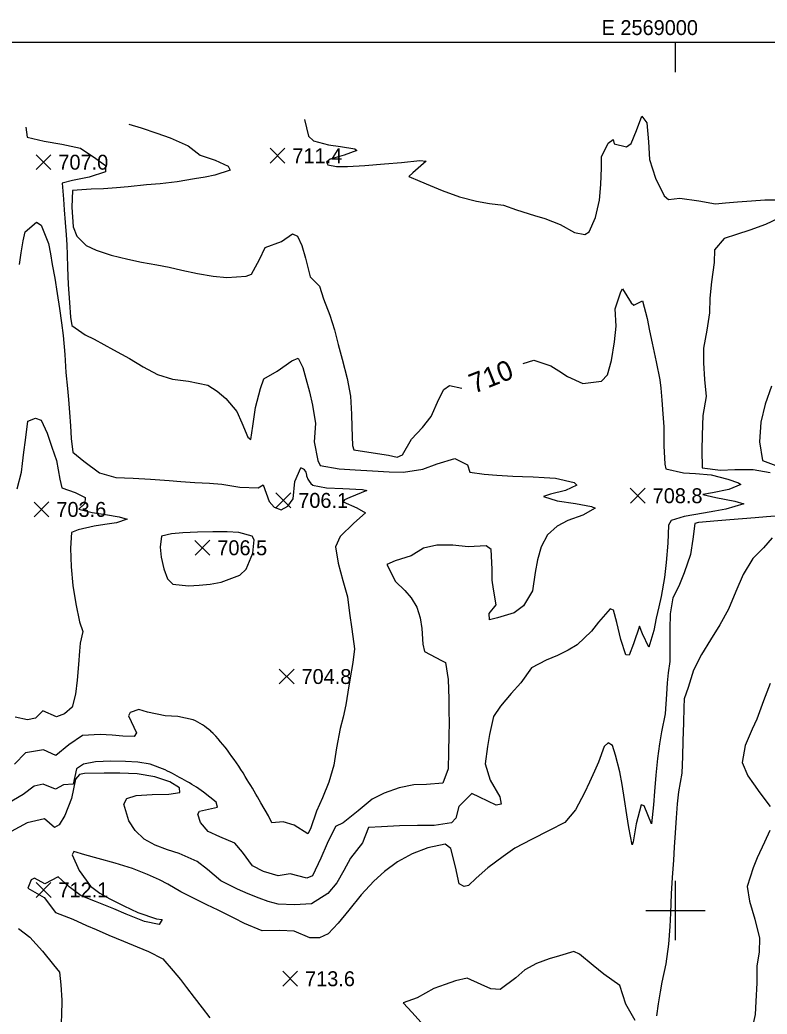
# Model space of a CAD drawing. Extents: x 2566079 to 2571326, y 424054 to 426896.
# Drawn here: x 2568340 to 2569092, y 425896 to 426896 of the extents above; entities that cross this region are included whole.
import ezdxf

# ---------------------------------------------------------------- set-up
doc = ezdxf.new("R2010")
doc.units = 0
for name, color, linetype in [('Contour_ADS_Label_Major', 7, 'Continuous'), ('Contour_ADS_Major', 7, 'Continuous'), ('Contour_ADS_Minor', 7, 'Continuous'), ('Contour_ADS_Spot_Elevation', 7, 'Continuous'), ('Contour_ADS_State_Plane_Border', 7, 'Continuous'), ('Contour_ADS_Tick', 7, 'Continuous')]:
    doc.layers.add(name, color=color, linetype=linetype)

# ---------------------------------------------------------------- blocks, each defined once
blk = doc.blocks.new('S890')
at = {"layer": 'Contour_ADS_Tick'}
for p, q in [((0, -0.5), (0, 0.5)), ((-0.5, 0), (0.5, 0))]:
    blk.add_line(p, q, dxfattribs=at)
blk = doc.blocks.new('S750')
at = {"layer": 'Contour_ADS_Spot_Elevation'}
for p, q in [((-0.5, 0.498), (0.5, -0.498)), ((-0.498, -0.5), (0.498, 0.5))]:
    blk.add_line(p, q, dxfattribs=at)

msp = doc.modelspace()

# ---------------------------------------------------------------- linework, layer by layer
at = {"layer": 'Contour_ADS_Major'}
for points in [[(2568449.5, 426791.4), (2568461.9, 426787.7), (2568477.7, 426782.6), (2568490.9, 426777.6), (2568509, 426769.6), (2568521.3, 426760.3), (2568536.4, 426755.2), (2568549.4, 426749.1), (2568551.5, 426745.1), (2568536.1, 426740.1), (2568526.1, 426738.3), (2568515.4, 426736.5), (2568497.9, 426733.6), (2568480.8, 426731.3), (2568467.3, 426730.4), (2568448.8, 426728.4), (2568437.1, 426727.3), (2568424, 426726.5), (2568411.4, 426725.9), (2568392.7, 426724.6), (2568392, 426708), (2568393.4, 426688.1), (2568397, 426678.9), (2568406.4, 426669.4), (2568416.6, 426664.6), (2568431.7, 426659.8), (2568448.3, 426655.7), (2568462.1, 426652.6), (2568477.5, 426649.8), (2568490.1, 426647.4), (2568502.9, 426644.6), (2568518.5, 426641.2), (2568534.2, 426638.5), (2568548, 426637.2), (2568567.6, 426638.4), (2568573, 426640.6), (2568580.9, 426655.4), (2568586.8, 426667.5), (2568603.3, 426673.3), (2568614.3, 426681.2), (2568619.3, 426678.6), (2568623.7, 426669.3), (2568627.3, 426656.6), (2568631.9, 426637.7), (2568641.5, 426628.4), (2568645.5, 426615.6), (2568651.8, 426599.3), (2568656.6, 426584.5), (2568660.3, 426569.6), (2568664.4, 426554.8), (2568669.3, 426535.4), (2568672.8, 426517.6), (2568673.5, 426499.5), (2568673.9, 426486.4), (2568674.6, 426468.2), (2568675.9, 426463.8), (2568691.2, 426461.3), (2568710.9, 426458.3), (2568719.6, 426456.3), (2568725.1, 426458.6), (2568734.1, 426474.4), (2568745.1, 426486.3), (2568754, 426497.3), (2568761.7, 426514.8), (2568766.7, 426524.5), (2568772.5, 426528.6), (2568784.7, 426525.9)], [(2568846.6, 426550.5), (2568857.2, 426554.1), (2568874.5, 426548.3), (2568882.4, 426543.3), (2568891.3, 426537.4), (2568906.7, 426530.6), (2568925.4, 426532.7), (2568931.6, 426539.2), (2568935.7, 426553.5), (2568938.6, 426572.5), (2568940.4, 426588.1), (2568939.4, 426605.5), (2568945.1, 426622.6), (2568946.6, 426625.7), (2568955.3, 426611.7), (2568958, 426609.2), (2568966.6, 426613.6), (2568971.5, 426596), (2568973.9, 426583.5), (2568976.4, 426571), (2568980.6, 426552.1), (2568984.1, 426534.3), (2568985.1, 426525.9), (2568986.2, 426513.7), (2568987.3, 426499.8), (2568988.1, 426487), (2568988.4, 426467.6), (2568989.1, 426449.2), (2568990.4, 426444.6), (2569008, 426440.5), (2569020.2, 426439.8), (2569036.1, 426438.4), (2569052.8, 426434.2), (2569063.3, 426430.6), (2569065.8, 426428.7), (2569053.6, 426423.7), (2569037.2, 426420.5), (2569027.5, 426418.7), (2569040.6, 426415.8), (2569059.8, 426412), (2569068.7, 426409.2), (2569050.8, 426403.8), (2569039.7, 426401.8), (2569028.1, 426399.8), (2569008.7, 426396.6), (2568995.8, 426392.5), (2568992.8, 426387.8), (2568992.3, 426369.6), (2568990.5, 426350.2), (2568989, 426335.2), (2568985.7, 426316), (2568983.3, 426305.7), (2568980.7, 426294.3), (2568978.1, 426281.9), (2568973.3, 426265.2), (2568966.7, 426278.6), (2568963.8, 426286.2), (2568957.8, 426268.3), (2568953.5, 426256.9), (2568950.1, 426257.3), (2568945, 426272.7), (2568941, 426289.8), (2568937.6, 426302.3), (2568934.2, 426303.5), (2568922.5, 426290.3), (2568915.5, 426281), (2568900.9, 426267.4), (2568891.9, 426262.1), (2568881, 426256.8), (2568869.9, 426251.9), (2568855.1, 426244.1), (2568844.2, 426229), (2568834.6, 426218.4), (2568823.6, 426205.6), (2568816.8, 426195.2), (2568812.5, 426177.2), (2568810.7, 426165.2), (2568808.3, 426147.7), (2568813.4, 426131.3), (2568822.9, 426114.3), (2568824.4, 426106.9), (2568819.5, 426106.1), (2568802.7, 426114.1), (2568795, 426117.7), (2568781.9, 426104.7), (2568778.9, 426092.9), (2568774.3, 426088.1), (2568756.9, 426085.7), (2568740.3, 426085.6), (2568722, 426085.3), (2568703.9, 426084.3), (2568690.9, 426083.4), (2568684.6, 426068), (2568672.7, 426052.6), (2568665.9, 426040.2), (2568658.9, 426027.8), (2568649.7, 426017.1), (2568633.3, 426006.6), (2568616.1, 426005.8), (2568599.7, 426006.3), (2568589.7, 426009.1)], [(2568589.7, 426009.1), (2568580.5, 426012.5), (2568569.7, 426016.8), (2568558.8, 426021.4), (2568541.9, 426029.7), (2568528.7, 426041.3), (2568518.3, 426049.2), (2568500, 426057.2), (2568488.2, 426061), (2568476, 426065.6), (2568464.8, 426071.9), (2568455.8, 426080.4), (2568449.3, 426090.1), (2568444.2, 426107.1), (2568447.5, 426112.7), (2568456.9, 426115.8), (2568472.8, 426116.8), (2568489.6, 426117.1), (2568500.6, 426118.9), (2568500.3, 426123.5), (2568490.8, 426129.5), (2568475.5, 426134.6), (2568457.8, 426137.4), (2568440.2, 426138.2), (2568424.6, 426138.2), (2568404.7, 426138), (2568399.6, 426137), (2568395.8, 426132.1), (2568391.5, 426112.8), (2568384.9, 426095.5), (2568379.1, 426086.2), (2568374.5, 426083.6), (2568364.3, 426092.1), (2568347, 426088.2), (2568330.8, 426079.5)], [(2568338.3, 425981.8), (2568349.5, 425973), (2568362.5, 425958.9), (2568373.6, 425945.3), (2568379.5, 425938), (2568380.8, 425925.3), (2568381.9, 425909.7), (2568381.7, 425893.8), (2568380.6, 425877.8), (2568377.6, 425861.3), (2568372.3, 425845.4), (2568371.3, 425838.1), (2568378.8, 425820.9), (2568385.3, 425812.2), (2568397.8, 425805.3), (2568405.8, 425802.5), (2568406.5, 425802.3)]]:
    msp.add_lwpolyline(points, dxfattribs=at)
at = {"layer": 'Contour_ADS_Minor'}
for points in [[(2568626.3, 426796.2), (2568630.5, 426779.4), (2568635.5, 426774.6), (2568650.4, 426770.6), (2568662.7, 426768.9), (2568677.1, 426766.6), (2568679, 426765), (2568666.1, 426760.3), (2568652.3, 426756.1), (2568648.5, 426753.4), (2568649.7, 426750.5), (2568658.4, 426749), (2568669.7, 426749), (2568687.1, 426750), (2568706.8, 426751.5), (2568723.9, 426753), (2568742.5, 426755), (2568748.7, 426754.1), (2568735.3, 426742.4), (2568731.4, 426738.9), (2568742.5, 426734.1), (2568752.9, 426729.6), (2568765.1, 426724.6), (2568782.5, 426718.2), (2568799.5, 426714), (2568812.7, 426711.8), (2568826.7, 426709.8), (2568840, 426705.2), (2568858, 426699.4), (2568868.3, 426696.6), (2568883.7, 426690.6), (2568898.3, 426682.6), (2568908.6, 426680.5), (2568913.2, 426683.1), (2568919.3, 426697.5), (2568923.6, 426715.1), (2568924.7, 426730.9), (2568925.6, 426747.4), (2568925.4, 426758.5), (2568932.1, 426772.5), (2568937.2, 426775.9), (2568938.3, 426771.8), (2568950.8, 426768.7), (2568955.3, 426772.1), (2568960.7, 426785.1), (2568966.1, 426799.4), (2568971, 426792.9), (2568972.7, 426773.8), (2568973.9, 426755.9), (2568979.9, 426737.3), (2568988.5, 426719.4), (2568993.1, 426715.5), (2569004.4, 426716.9), (2569023.5, 426714.4), (2569040.3, 426711.3), (2569050.4, 426712.3), (2569062.3, 426713.2), (2569076.6, 426714.3), (2569089.9, 426715.2), (2569109.5, 426715.4)], [(2568345.5, 426788.6), (2568347.1, 426778.5), (2568364.1, 426774.5), (2568381.8, 426771.2), (2568400.8, 426767.3), (2568416, 426757.1), (2568425.9, 426749.8), (2568425.8, 426743.6), (2568409.4, 426738.3), (2568392.5, 426734.8), (2568382.3, 426732.2), (2568383.4, 426715.9), (2568384.4, 426705.2), (2568385.4, 426692.4), (2568386.3, 426680.1), (2568386.8, 426670), (2568387.2, 426660), (2568387.6, 426647.3), (2568388.4, 426630.2), (2568389.5, 426612), (2568390.6, 426597.1), (2568392, 426588.7), (2568405.5, 426579.5), (2568414.3, 426575), (2568424.2, 426569.8), (2568434, 426564.4), (2568450.1, 426555.7), (2568463.9, 426547.3), (2568478.1, 426539.5), (2568493.5, 426534.7), (2568509.5, 426532.7), (2568528.8, 426528.8), (2568538.4, 426522.9), (2568547, 426515.3), (2568558, 426502.2), (2568563.2, 426490.9), (2568569.4, 426476.4), (2568572.1, 426474.1), (2568574.4, 426487.5), (2568576.8, 426506.4), (2568582.1, 426525.3), (2568585.2, 426535.3), (2568598.7, 426542.9), (2568613.4, 426553.2), (2568620, 426555.8), (2568624.6, 426546.6), (2568627.8, 426535.5), (2568631.3, 426521.9), (2568634.3, 426508.7), (2568637.3, 426490.1), (2568636, 426471.9), (2568639.7, 426452.9), (2568642.1, 426448), (2568661.1, 426444.7), (2568677.5, 426443.6), (2568694.7, 426442.7), (2568711.7, 426441.5), (2568725.9, 426441.1), (2568745.4, 426444.3), (2568759.8, 426449.6), (2568777.8, 426455.1), (2568790.5, 426448.5), (2568793, 426441.2), (2568807.3, 426439.1), (2568820.2, 426438.1), (2568836.3, 426437.1), (2568845.9, 426436.8), (2568856.5, 426436.5), (2568867.8, 426436), (2568879.2, 426435), (2568897.8, 426430.7), (2568900.6, 426428), (2568889.3, 426422.8), (2568874, 426419.1), (2568867.2, 426416.8), (2568880.9, 426412.2), (2568899.2, 426409.6), (2568915.3, 426406.5), (2568919.1, 426404.9), (2568906.6, 426397.9), (2568891.6, 426392.4), (2568880.8, 426386.7), (2568871.1, 426378.1), (2568864.6, 426366.2), (2568860.9, 426352.9), (2568858.8, 426340.2), (2568855.8, 426321.8), (2568846.8, 426306.5), (2568837.5, 426299.5), (2568820.7, 426294.5), (2568812.7, 426292.7), (2568812.2, 426298.8), (2568819.3, 426307.5), (2568816.8, 426323.5), (2568815.3, 426332.5), (2568815.5, 426343.7), (2568814.2, 426363.4), (2568809.2, 426367.2), (2568791.2, 426366.2), (2568775.7, 426367.8), (2568759.6, 426367.7)], [(2568339.1, 426650.3), (2568340.8, 426661.9), (2568342.8, 426674), (2568345.1, 426683.2), (2568356.3, 426692.7), (2568361.2, 426689.8), (2568368.6, 426671.5), (2568370.5, 426660.9), (2568372.3, 426650.4), (2568374.7, 426636.6), (2568377.2, 426621.2), (2568379.6, 426605.8), (2568381.6, 426591.4), (2568383.2, 426578.7), (2568384.8, 426559.6), (2568386, 426541.4), (2568387.6, 426525.4), (2568388.6, 426514.2), (2568389.6, 426501.4), (2568390.5, 426487.7), (2568391.3, 426475.1), (2568393.1, 426461.4), (2568404.2, 426452.2), (2568419.7, 426440.5), (2568436.4, 426436), (2568453.6, 426435.3), (2568471.1, 426434.2), (2568490, 426432.7), (2568501.8, 426431.8), (2568516, 426430.9), (2568530.5, 426430.1), (2568542.9, 426429.1), (2568561.3, 426426), (2568579.6, 426425.3), (2568584.6, 426428.3), (2568590.7, 426411.6), (2568595.9, 426406), (2568602.8, 426403.2), (2568609.6, 426407.1), (2568615, 426414.2), (2568616.6, 426431.7), (2568622.5, 426445.4)], [(2569104.2, 426696.9), (2569090.8, 426690.6), (2569074.9, 426684.8), (2569061.3, 426680.3), (2569049.1, 426676.3), (2569039.3, 426664.9), (2569039.1, 426652.1), (2569036.4, 426632.7), (2569034.5, 426616.5), (2569034.3, 426601.5), (2569031.6, 426584.1), (2569028.3, 426566.1), (2569028.2, 426551.3), (2569029.3, 426534.4), (2569031, 426517.4), (2569027.5, 426498.3), (2569026.7, 426478.5), (2569026.4, 426463.2), (2569026.7, 426445.7), (2569045.5, 426443.2), (2569059.7, 426444), (2569078.1, 426444), (2569095.4, 426440.8)], [(2569096.6, 426527.9), (2569090.4, 426509.6), (2569085.9, 426491.7), (2569084.7, 426471.8), (2569087.8, 426452.8), (2569106.5, 426446)], [(2568336.8, 426424.4), (2568341.1, 426441.1), (2568342.3, 426450), (2568343.7, 426461.4), (2568345.2, 426473.3), (2568347.6, 426492.7), (2568355.5, 426495.5), (2568360.9, 426493.4), (2568367.1, 426480.3), (2568371.9, 426466.3), (2568376.6, 426452.8), (2568380, 426434.3), (2568381.9, 426425.4), (2568395.2, 426420.7), (2568405.4, 426415.7), (2568405.2, 426409.7), (2568398.9, 426403.8), (2568412.5, 426400.7), (2568425.9, 426398.7), (2568439.5, 426396.3), (2568447.6, 426394), (2568437, 426390.3), (2568425.3, 426388.6), (2568414.4, 426386.7), (2568398.5, 426383.3), (2568391.5, 426380.5), (2568390.6, 426364.6), (2568391.3, 426345.8), (2568393, 426327.1), (2568396, 426308.7), (2568399.7, 426290.4), (2568403, 426280.8), (2568400.5, 426269), (2568399.7, 426260.9), (2568398.6, 426247.5), (2568397.2, 426231.8), (2568395.6, 426217.9), (2568392.4, 426204.6), (2568384.5, 426198.1), (2568376.5, 426195), (2568362.6, 426200.9), (2568355.4, 426193.5), (2568347.4, 426191.8), (2568335, 426194.6)], [(2568634.5, 426428.1), (2568648.4, 426425.5), (2568665, 426424.9), (2568684.6, 426423.9), (2568689.1, 426422.9), (2568671.9, 426415.7), (2568666.6, 426413.5), (2568665.3, 426411.4), (2568678.9, 426405.2), (2568687.8, 426400.2), (2568676, 426390), (2568662.3, 426376.5), (2568657.6, 426365.9), (2568660.3, 426349.6), (2568664.9, 426332.2), (2568669.5, 426315.6), (2568671.7, 426299.2), (2568673.9, 426283.2), (2568676.8, 426263.5), (2568674.9, 426249.5), (2568672.1, 426232.3), (2568670.1, 426219.9), (2568667.8, 426207), (2568665.1, 426194.7), (2568662.4, 426183.3), (2568658.6, 426163.7), (2568655.9, 426146.4), (2568650.9, 426129), (2568644.4, 426113.3), (2568638.4, 426100.1), (2568632.3, 426082.2), (2568629.8, 426077), (2568615.8, 426085.9), (2568604.8, 426089.4), (2568593.4, 426088.2), (2568589.9, 426095.2), (2568582.4, 426108.5)], [(2569042.6, 426392.2), (2569023.3, 426390.5), (2569019.5, 426389.4), (2569017.3, 426373.7), (2569015.1, 426358.3), (2569008.9, 426339.8), (2569003.2, 426326.6), (2568997.3, 426314.8), (2568994.7, 426298.7), (2568994.2, 426283.2), (2568994.3, 426266.6), (2568994.2, 426250.6), (2568992.5, 426239.2), (2568991.7, 426229), (2568991, 426217.7), (2568989.5, 426197.9), (2568985.9, 426179.7), (2568983.9, 426167.8), (2568981.9, 426153.1), (2568980.1, 426136.3), (2568978.8, 426119.8), (2568977.8, 426106.5), (2568975.8, 426087.2), (2568968.3, 426105.5), (2568965.5, 426106.3), (2568960.4, 426087.3), (2568957.4, 426069.2), (2568956.3, 426066.1), (2568952.9, 426083.6), (2568951.1, 426096.2), (2568948.8, 426111.6), (2568946.2, 426126.9), (2568943.8, 426139.4), (2568939.6, 426156.2), (2568936.4, 426166.1), (2568932.1, 426168.6), (2568928, 426165.2), (2568922.6, 426149.4), (2568918.5, 426140.1), (2568913.5, 426129), (2568908.5, 426118.5), (2568899.4, 426101.3), (2568888.6, 426088.7), (2568872.6, 426080.4), (2568855, 426071.5), (2568838.2, 426062.7), (2568826.3, 426054.2), (2568811, 426043), (2568799.3, 426032.5), (2568791.6, 426025.2), (2568787, 426024), (2568782, 426026.7), (2568778.3, 426044.1), (2568773.6, 426062.4), (2568767.9, 426066.7), (2568750.7, 426063.1), (2568734.9, 426056.9), (2568720, 426048.9), (2568706.9, 426039.4), (2568696.1, 426029.6), (2568683.3, 426015.7), (2568670.8, 426000.3), (2568660.2, 425987.2), (2568650.2, 425976.6), (2568641.5, 425972.4), (2568631.7, 425972.6), (2568616, 425979.1), (2568601.6, 425980), (2568583.8, 425979.5), (2568566, 425987), (2568555.5, 425992.3), (2568539.3, 426000.3), (2568527.8, 426005.7), (2568519.1, 426009.9), (2568501.7, 426018.8), (2568488.6, 426026.6), (2568480.3, 426030.9), (2568468.3, 426036.3), (2568453.2, 426042.1), (2568435.7, 426047.6), (2568418.6, 426052.3), (2568405.1, 426056), (2568394, 426059.5), (2568392.2, 426056), (2568399.3, 426040.3), (2568410.9, 426024.5), (2568420.2, 426017.5), (2568430.2, 426011.7), (2568444.3, 426004.7), (2568458.4, 425997.9), (2568477.4, 425991.7), (2568483, 425990.8), (2568480, 425985.9), (2568465.2, 425988.8), (2568446.7, 425996.3), (2568434.1, 426001.5), (2568415.7, 426009), (2568401.4, 426014.8), (2568389.2, 426023.8), (2568378.3, 426033.9), (2568364.7, 426026.9)], [(2569100.5, 426396.9), (2569091.6, 426396.2), (2569080.3, 426395.2), (2569067.6, 426394.2), (2569054.6, 426393.2), (2569042.6, 426392.2)], [(2569097.5, 426375.1), (2569088.7, 426364.9), (2569078, 426354.4), (2569068, 426338.1), (2569060.9, 426321.2), (2569053.5, 426303.4), (2569044.7, 426287.6), (2569035.1, 426272.6), (2569026.2, 426257.6), (2569018.3, 426242), (2569012.7, 426224.3), (2569008.8, 426213.2), (2569008.4, 426204.2), (2569007.9, 426188.8), (2569007.3, 426170.7), (2569007, 426155.1), (2569006.3, 426138.2), (2569002.9, 426119.4), (2569001.7, 426107.5), (2569000.6, 426093.3), (2568999.7, 426078.3), (2568998.8, 426063.7), (2568997.9, 426050.6), (2568996.8, 426033.2), (2568995.7, 426016.6), (2568994.9, 425997.4), (2568994.2, 425984), (2568992.9, 425966.2), (2568990.3, 425946.4), (2568986.1, 425927.9), (2568984.4, 425918.1)], [(2568759.6, 426367.7), (2568746.3, 426364.8), (2568733.6, 426356.9), (2568717.5, 426352.1), (2568709.3, 426348.1), (2568718.1, 426331), (2568727.3, 426322.2), (2568733.7, 426314.6), (2568739.3, 426305.3), (2568742.8, 426294.6), (2568744.5, 426283.9), (2568745.6, 426268.1), (2568747.3, 426260.8), (2568764.2, 426251.7), (2568768.3, 426249.5), (2568770.9, 426232.5), (2568771.7, 426213), (2568771.8, 426201.4), (2568771.9, 426188.5), (2568771.8, 426176.5), (2568771.4, 426159.4), (2568770.9, 426142.6), (2568765.8, 426128.2), (2568749.3, 426126.9), (2568736.6, 426126.6), (2568721.6, 426123.3), (2568706.7, 426118), (2568694.4, 426112.2), (2568680.3, 426100.4), (2568665.4, 426088.3), (2568657.4, 426084.7), (2568649.1, 426067.5), (2568642.9, 426052.6), (2568634.3, 426034.9), (2568628.8, 426032.7), (2568612, 426037), (2568599.8, 426035), (2568584.9, 426039.1), (2568573.8, 426044.8), (2568563.9, 426058.7), (2568556.3, 426067.6), (2568540.9, 426074.2), (2568529.3, 426079.6), (2568521.5, 426088.7), (2568519, 426097.1), (2568520.6, 426099.9), (2568538.7, 426104), (2568537.2, 426109.2), (2568524.6, 426119.2)], [(2569095.3, 426228.5), (2569088.8, 426210.9), (2569082, 426192.7), (2569077.3, 426182.6), (2569070.2, 426166.1), (2569067, 426149.1), (2569072.8, 426135.7), (2569078.5, 426127.4), (2569085.1, 426118.3), (2569095.3, 426104.6)], [(2568514.2, 426192), (2568498.7, 426195.4), (2568485.8, 426195.8), (2568468.3, 426199.5), (2568459.5, 426202.2), (2568450.8, 426199.3), (2568449.2, 426195.9), (2568457, 426178.7), (2568454.7, 426175), (2568443.3, 426175.5), (2568432.7, 426176.5), (2568420.6, 426177.3), (2568402.6, 426176.2), (2568388.8, 426166.9), (2568375.9, 426156.1), (2568363.4, 426161.8), (2568345.3, 426158.8), (2568334.1, 426147.4)], [(2568485.9, 426141.5), (2568470.8, 426147.3), (2568458.6, 426149.4), (2568446, 426149.9), (2568431.1, 426150.2), (2568415.9, 426149.7), (2568403.6, 426147.4), (2568396.7, 426142.5), (2568393.2, 426127.1), (2568383.5, 426126.5), (2568375.6, 426122.1), (2568363.1, 426127.2), (2568354, 426125.1), (2568343, 426116.6), (2568327.5, 426107.6)], [(2569094.9, 426080.5), (2569089.6, 426068.9), (2569082.2, 426053.1), (2569078.2, 426042.9), (2569072.2, 426024.3), (2569074.5, 426009.4), (2569079.9, 425991.4), (2569084.6, 425972), (2569084.2, 425957.9), (2569081.9, 425944.2), (2569082, 425927.1), (2569080.8, 425908.4)], [(2568364.7, 426026.9), (2568354.4, 426032.6), (2568351.1, 426030.8), (2568347.8, 426022.3), (2568364.1, 426013.2), (2568375.5, 425997.9), (2568393.1, 425991.3), (2568406.7, 425984.9), (2568416.3, 425980.8), (2568429.3, 425975.3), (2568444, 425969.2), (2568457.9, 425963.5), (2568469.1, 425958.7), (2568483.5, 425951.4), (2568493.9, 425939.4), (2568501.3, 425930.6), (2568507.6, 425922.5), (2568515.1, 425912.5), (2568523.1, 425902), (2568531, 425891.9)], [(2568959.4, 425889.1), (2568950, 425905.8), (2568943.9, 425924.4), (2568927.9, 425936), (2568917.1, 425944.7), (2568903.3, 425956.2), (2568897.6, 425958.6), (2568883.3, 425954.5), (2568872.6, 425951.3), (2568860.1, 425946.7), (2568848.4, 425940.3), (2568839.2, 425932.2), (2568823.5, 425920.3), (2568814, 425921.3), (2568804.1, 425925.6), (2568790.1, 425931.9), (2568778.3, 425929.1), (2568768.1, 425925.6), (2568756.7, 425921.5), (2568739.7, 425912), (2568725.6, 425907.1), (2568734.7, 425897.2), (2568743.5, 425887.5)], [(2568984.4, 425918.1), (2568982.7, 425906.1), (2568980.9, 425894)], [(2569080.8, 425908.4), (2569080.1, 425895.4), (2569076.8, 425880.2), (2569068.5, 425864.2), (2569058.8, 425847.6), (2569047.6, 425840.1), (2569037.2, 425823.3), (2569034.3, 425814.6), (2569020.6, 425802.2), (2569003.4, 425797), (2568996.8, 425787.7), (2568995.1, 425776.2), (2568999, 425765.4), (2568980, 425767.7), (2568965.8, 425768.4), (2568949.8, 425766.4), (2568959.1, 425760.3), (2568968.1, 425756), (2568984, 425748.5)]]:
    msp.add_lwpolyline(points, dxfattribs=at)
msp.add_lwpolyline([(2568492.2, 426379.3), (2568482.2, 426376.9), (2568480.8, 426365.6), (2568482.1, 426355.5), (2568484.5, 426343.8), (2568488.3, 426334), (2568493.7, 426328.6), (2568509.6, 426326.8), (2568520.1, 426327.5), (2568531.3, 426328.6), (2568542.4, 426330.5), (2568561.1, 426337.5), (2568567.7, 426343.5), (2568574.4, 426359.8), (2568575.5, 426373.1), (2568573.7, 426376.7), (2568560.1, 426380.4), (2568548.3, 426381.1), (2568534, 426381.2), (2568518.5, 426380.9), (2568503.8, 426380.3), (2568492.2, 426379.3)], close=True, dxfattribs=at)
for centre, radius, start, end in [((2568621.1, 426438), 7.56, 350.7542, 78.9802), ((2568649.4, 426444.8), 22.4, 201.2122, 228.4329), ((2568485.7, 426128.5), 69.6, 48.4975, 65.8617), ((2568413.7, 426060.1), 168.7, 35.6624, 45.5785), ((2568220.4, 425919.4), 407.8, 31.3556, 35.8763), ((2568390, 425936.1), 226.7, 59.4132, 64.9973), ((2568390.3, 425926.4), 235, 55.1383, 60.6743), ((2567793.6, 425657.8), 908.4, 29.7462, 31.4439)]:
    msp.add_arc(centre, radius, start, end, dxfattribs=at)
at = {"layer": 'Contour_ADS_State_Plane_Border'}
msp.add_line((2569000, 426843.7), (2569000, 426873.7), dxfattribs=at)
msp.add_lwpolyline([(2566079.3, 424077.1), (2571302.9, 424077.1), (2571302.9, 426873.7), (2566079.3, 426873.7), (2566079.3, 424077.1)], close=True, dxfattribs=at)

# ---------------------------------------------------------------- block references
at = {"layer": 'Contour_ADS_Spot_Elevation', "xscale": 15, "yscale": 15}
for p in [(2568363.4, 426753.2), (2568599.1, 426759.7), (2568605, 426412.8), (2568962, 426417.5), (2568361.4, 426403.7), (2568523.5, 426365.1), (2568608.3, 426235.5), (2568363.5, 426020.7), (2568611.9, 425931.3)]:
    msp.add_blockref('S750', p, dxfattribs=at)
at = {"layer": 'Contour_ADS_Tick', "xscale": 60, "yscale": 60}
msp.add_blockref('S890', (2569000, 426000), dxfattribs=at)

# ---------------------------------------------------------------- texts
at = {"layer": 'Contour_ADS_Label_Major'}
msp.add_text('710', height=20, rotation=21.6086, dxfattribs=at).set_placement((2568797, 426520))
at = {"layer": 'Contour_ADS_Spot_Elevation'}
for s, p in [('707.0', (2568378.4, 426745.7)), ('711.4', (2568614.1, 426752.2)), ('706.1', (2568620, 426405.3)), ('708.8', (2568977, 426410)), ('703.6', (2568376.4, 426396.2)), ('706.5', (2568538.5, 426357.6)), ('704.8', (2568623.3, 426228)), ('712.1', (2568378.5, 426013.2)), ('713.6', (2568626.9, 425923.8))]:
    msp.add_text(s, height=15, dxfattribs=at).set_placement(p)
at = {"layer": 'Contour_ADS_State_Plane_Border'}
msp.add_text(' E 2569000', height=15, dxfattribs=at).set_placement((2568920, 426881.2))

doc.saveas('drawing.dxf')
